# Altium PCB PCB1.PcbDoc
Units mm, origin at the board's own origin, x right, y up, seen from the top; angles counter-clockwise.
Board outline 48.01 x 48.26 mm, 2 copper layers (Top Layer, Bottom Layer); 27 components, 29 nets, 112 pads, 21 vias.
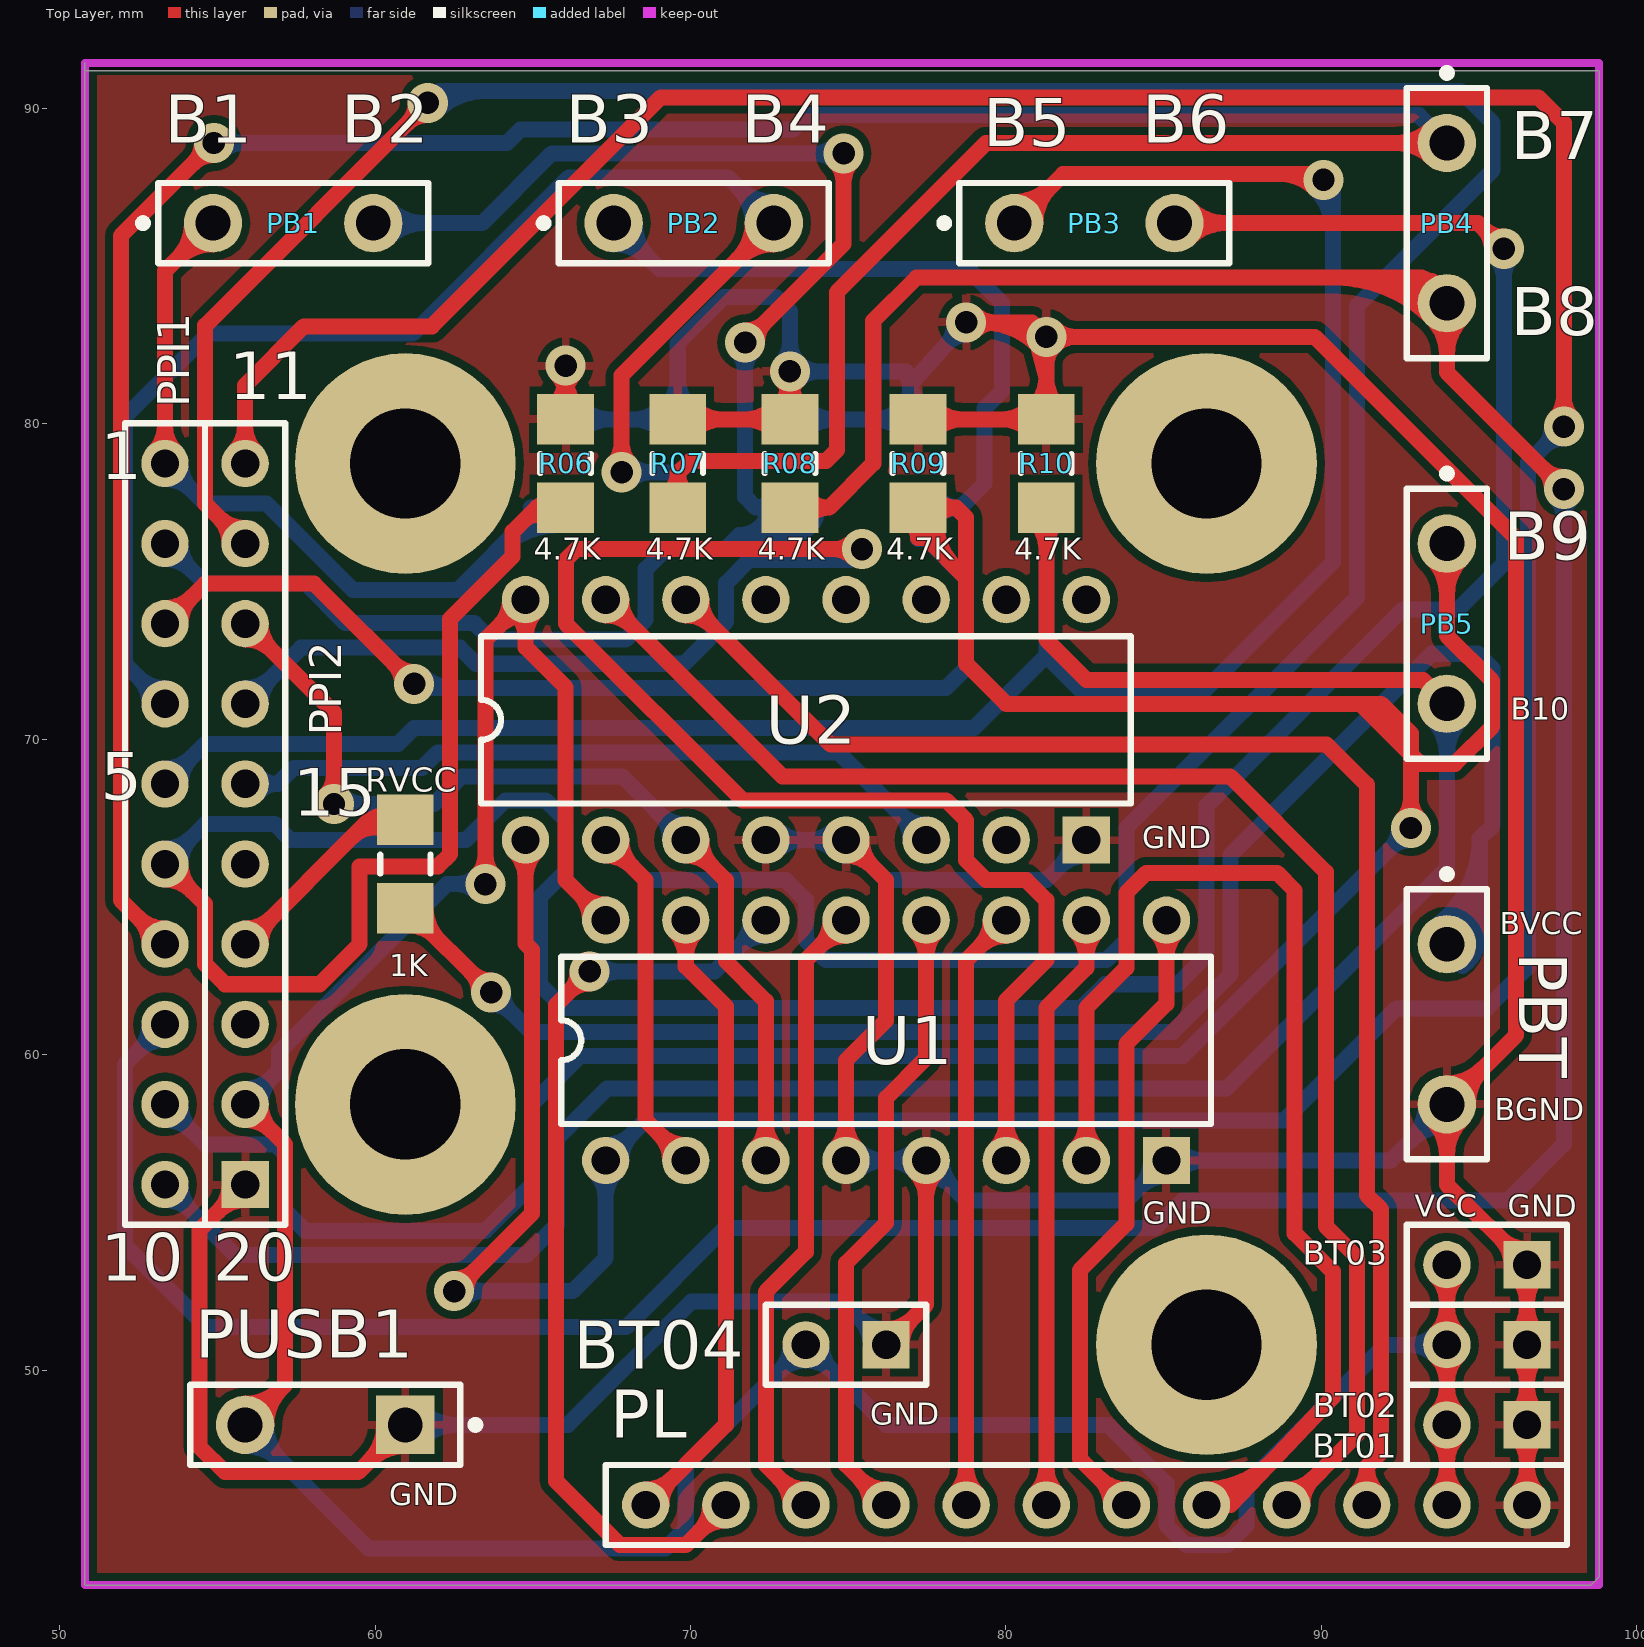
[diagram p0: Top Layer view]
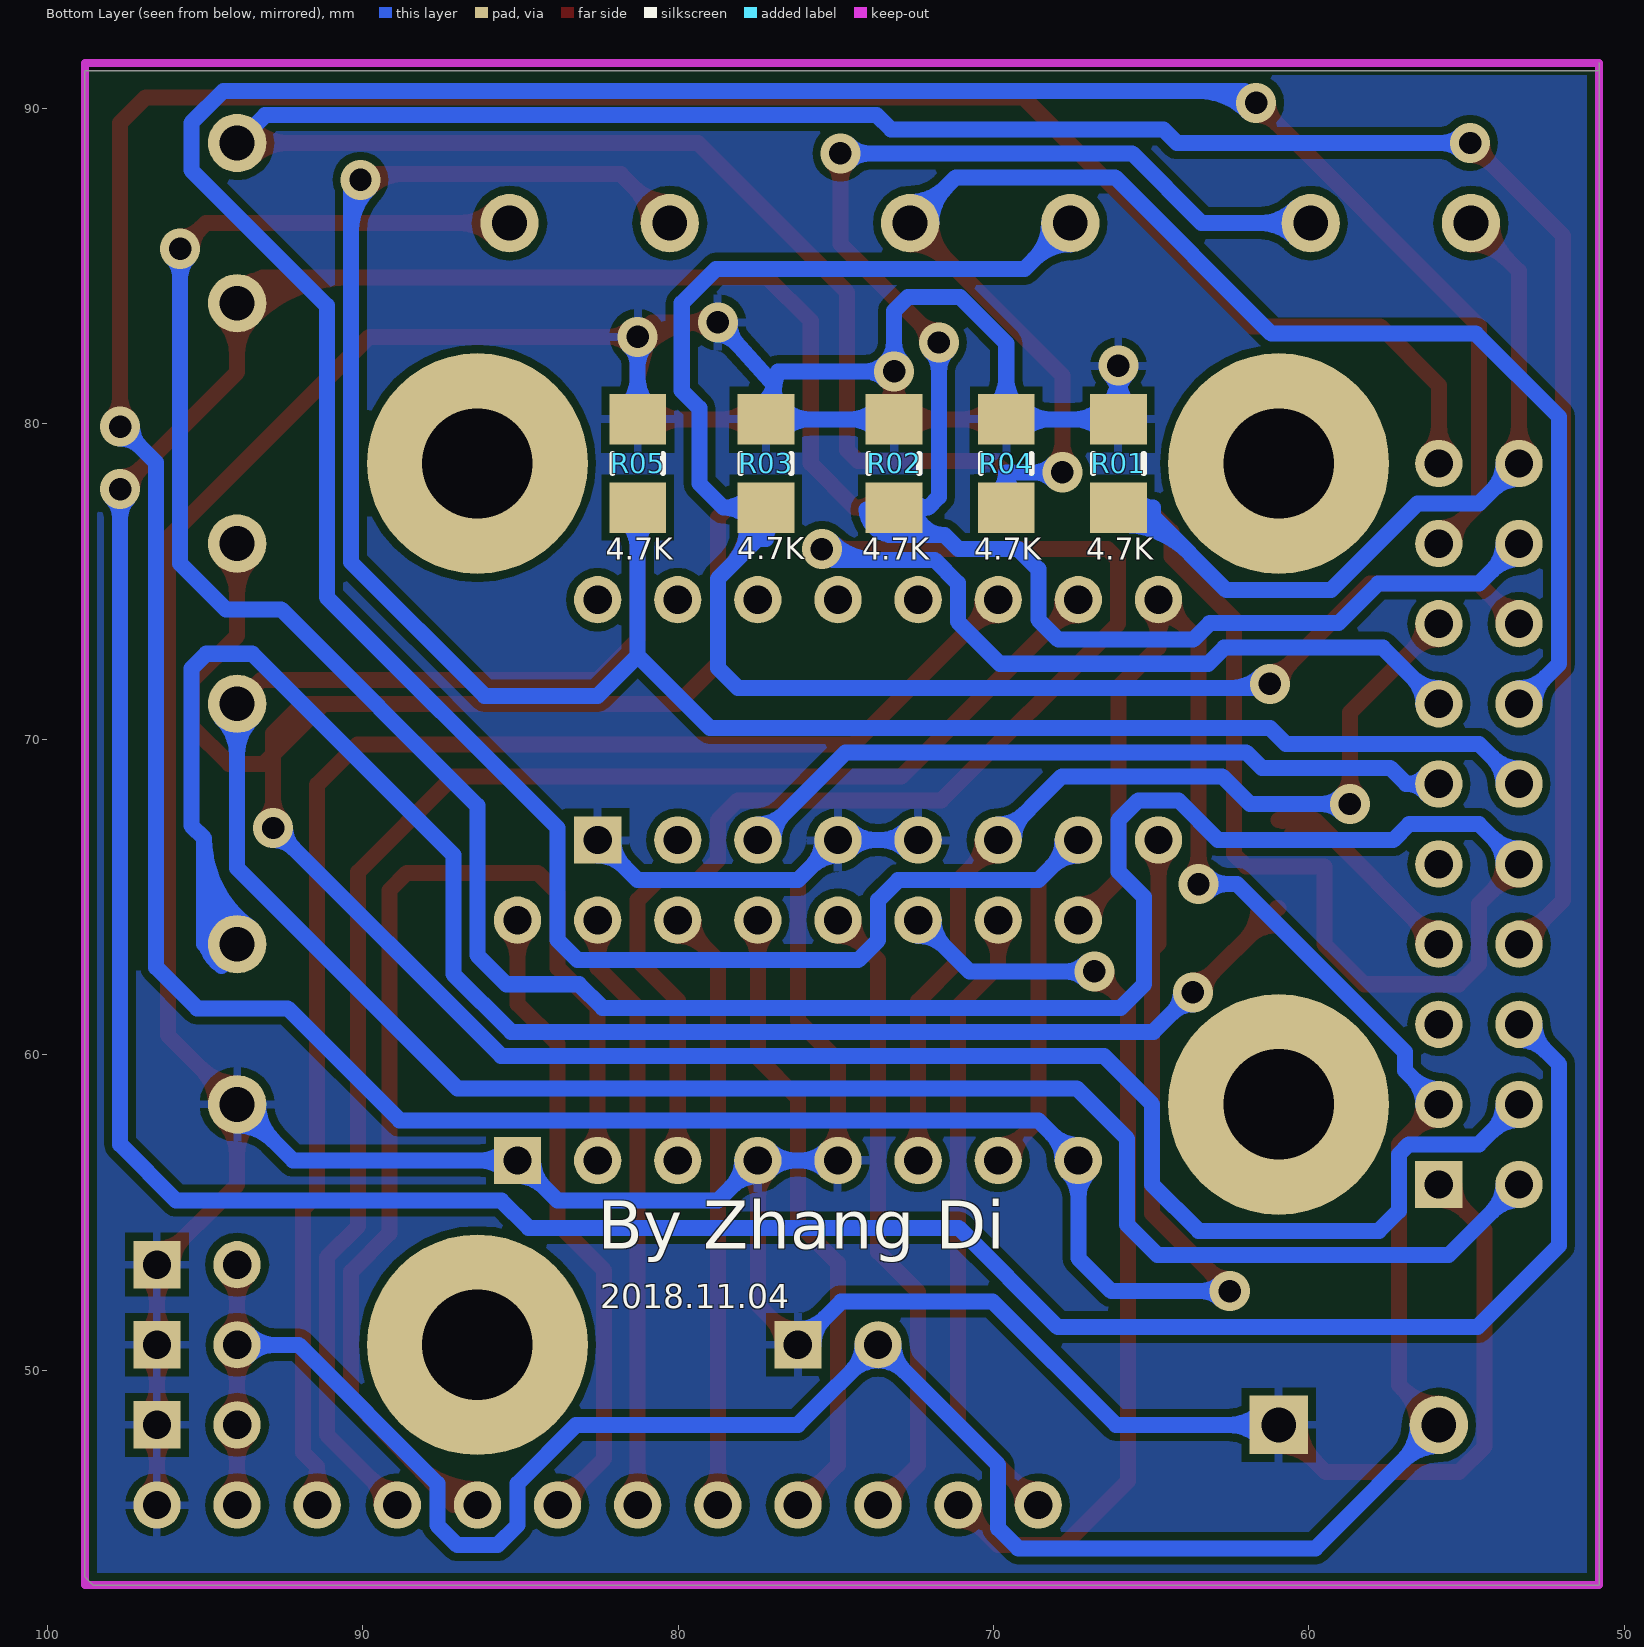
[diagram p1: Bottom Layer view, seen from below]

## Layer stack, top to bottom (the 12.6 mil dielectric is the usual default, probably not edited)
Top Layer: signal copper 0.0356
Dielectric: dielectric 0.32, FR-4, Dk 4.8
Bottom Layer: signal copper 0.0356

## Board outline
51.054,91.186 98.806,91.186 98.806,43.434 98.552,43.18 50.8,43.18 50.8,91.44 50.8,91.186

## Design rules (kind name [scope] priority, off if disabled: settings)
Clearance [All] p1: gap=0.254
ComponentClearance [All] p1: gap=0.254 collisioncheckmode=3 verticalgap=0.254
PolygonConnect [All] p1: connectstyle=Relief reliefconductorwidth=0.254 reliefentries=4 polygonreliefangle="90 Angle"
RoutingVias [All] p1: holewidth=0.711 width=1.27 viastyle="Through Hole" minholewidth=0.711 minwidth=1.27 maxholewidth=0.711 maxwidth=1.27
SolderMaskExpansion [All] p1: expansion=0.102
TestPointUsage [All] p1: valid=0 allowmultiple=FALSE
Testpoint [All] p1: side=15 testpointundercomponent=TRUE minsize=1.016 maxsize=2.54 preferedsize=1.524 minholesize=0 maxholesize=1.016 preferedholesize=0.813 testpointgrid=0.025 style=1023 order=0-112345678
Width Width_2 [All] p1: maxlimit=0.762 minlimit=0.381 preferedwidth=0.508
Width Width_1 [InNet('VCC')] p2: maxlimit=0.762 minlimit=0.508 preferedwidth=0.762
Width [InNet('GND')] p3: maxlimit=0.762 minlimit=0.508 preferedwidth=0.762
18 further rules are at their usual default settings.

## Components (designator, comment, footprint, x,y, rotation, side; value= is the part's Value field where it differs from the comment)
BT01 "Header 2" HDR1X2 96.52,48.26 r180 top
BT02 "Header 2" HDR1X2 96.52,50.8 r180 top
BT03 "Header 2" HDR1X2 96.52,53.34 r180 top
BT04 "Header 2" HDR1X2 76.2,50.8 r180 top
PB1 "Header 2" SPST-2#1 57.404,86.36 r0 top
PB2 "Header 2" SPST-2#1 70.104,86.36 r0 top
PB3 "Header 2" SPST-2#1 82.804,86.36 r0 top
PB4 "Header 2" SPST-2#1 93.98,86.36 r270 top
PB5 "Header 2" SPST-2#1 93.98,73.66 r270 top
PBT "Header 2" SPST-2#1 93.98,60.96 r270 top
PL "Header 12" HDR1X12 68.58,45.72 r0 top
PPI1 "Header 10" HDR1X10#1 53.34,78.74 r270 top
PPI2 "Header 10" HDR1X10#2 55.88,78.74 r270 top
PUSB1 "Header 2" SPST-2#2 58.42,48.26 r180 top
R01 "Res1" 3216[1206] 66.04,78.74 r270 bottom
R02 "Res1" 3216[1206] 73.152,78.74 r270 bottom
R03 "Res1" 3216[1206] 77.216,78.74 r270 bottom
R04 "Res1" 3216[1206] 69.596,78.74 r270 bottom
R05 "Res1" 3216[1206] 81.28,78.74 r270 bottom
R06 "Res1" 3216[1206] 66.04,78.74 r270 top
R07 "Res1" 3216[1206] 69.596,78.74 r270 top
R08 "Res1" 3216[1206] 73.152,78.74 r270 top
R09 "Res1" 3216[1206] 77.216,78.74 r270 top
R10 "Res1" 3216[1206] 81.28,78.74 r270 top
RVCC "Res1" 3216[1206] 60.96,66.04 r90 top
U1 "SN74HC138D" DIP-16 76.2,60.452 r0 top
U2 "SN74HC138D" DIP-16 73.66,70.612 r0 top

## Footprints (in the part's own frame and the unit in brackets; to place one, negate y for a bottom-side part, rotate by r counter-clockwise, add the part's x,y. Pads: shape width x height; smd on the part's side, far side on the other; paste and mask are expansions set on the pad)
3216[1206] [mm] "Chip Resistor; Body 3.2 x 1.6 mm (LxW typ)"
  rect 1.6x1.8 smd: 1(-1.4,0) 2(1.4,0)
  silkscreen extent -0.3,-0.8 0.3,0.8
DIP-16 [mm] "DIP; 16 Leads; Row Spacing 7.62 mm; Pitch 2.54 mm"
  round 1.5 hole 0.9: 1(-8.89,-3.81) 2(-6.35,-3.81) 3(-3.81,-3.81) 4(-1.27,-3.81) 5(1.27,-3.81) 6(3.81,-3.81) 7(6.35,-3.81) 9(8.89,3.81) 10(6.35,3.81) 11(3.81,3.81) 12(1.27,3.81) 13(-1.27,3.81) 14(-3.81,3.81) 15(-6.35,3.81) 16(-8.89,3.81)
  rect 1.5x1.5 hole 0.9: 8(8.89,-3.81)
  silkscreen extent -10.3,-2.65 10.3,2.65
HDR1X2 [mm] "Connector; Header; 2 Position"
  rect 1.5x1.5 hole 0.9: 1(0,0)
  round 1.5 hole 0.9: 2(2.54,0)
  silkscreen extent -1.27,-1.27 3.81,1.27
HDR1X10#1 [mm] "Connector; Header; 10 Position"
  round 1.5 hole 0.9: 1(0,0) 2(2.54,0) 3(5.08,0) 4(7.62,0) 5(10.16,0) 6(12.7,0) 7(15.24,0) 8(17.78,0) 9(20.32,0) 10(22.86,0)
  silkscreen extent -1.27,-1.27 24.13,1.27
HDR1X10#2 [mm] "Connector; Header; 10 Position"
  round 1.5 hole 0.9: 1(0,0) 2(2.54,0) 3(5.08,0) 4(7.62,0) 5(10.16,0) 6(12.7,0) 7(15.24,0) 8(17.78,0) 9(20.32,0)
  rect 1.5x1.5 hole 0.9: 10(22.86,0)
  silkscreen extent -1.27,-1.27 24.13,1.27
HDR1X12 [mm] "Connector; Header; 12 Position"
  round 1.5 hole 0.9: 1(0,0) 2(2.54,0) 3(5.08,0) 4(7.62,0) 5(10.16,0) 6(12.7,0) 7(15.24,0) 8(17.78,0) 9(20.32,0) 10(22.86,0) 11(25.4,0) 12(27.94,0)
  silkscreen extent -1.27,-1.27 29.21,1.27
SPST-2#1 [mm] "Circuit Breaker; 2 Leads"
  round 1.85 hole 1.1: 1(-2.54,0) 2(2.54,0)
  silkscreen extent -4.89,-1.27 4.28,1.27
SPST-2#2 [mm] "Circuit Breaker; 2 Leads"
  rect 1.85x1.85 hole 1.1: 1(-2.54,0)
  round 1.85 hole 1.1: 2(2.54,0)
  silkscreen extent -4.89,-1.27 4.28,1.27

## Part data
BT01 BT02 BT03 BT04 PB1 PB2 PB3 PB4 PB5 PBT PUSB1: "Header, 2-Pin"
PL: "Header, 12-Pin"
PPI1 PPI2: "Header, 10-Pin"
R01 R02 R03 R04 R05 R06 R07 R08 R09 R10 RVCC: "Resistor"
U1 U2: "3-Line to 8-Line Decoder / Demultiplexer"

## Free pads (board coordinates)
  round 7 hole 3.5: 0(86.36,78.74) 1(60.96,78.74) 3(86.36,50.8)
  round 7 hole 3.5 paste+0: 2(60.96,58.42)

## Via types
v1: diameter 1.27, hole 0.711, Top Layer to Bottom Layer, 21 vias

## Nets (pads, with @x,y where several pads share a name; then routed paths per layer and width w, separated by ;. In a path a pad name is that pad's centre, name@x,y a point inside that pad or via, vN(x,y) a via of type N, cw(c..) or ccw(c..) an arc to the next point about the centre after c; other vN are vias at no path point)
GND: BT01.1 BT02.1 BT03.1 BT04.1 PBT.2 PL.12 PPI2.10 PUSB1.1 R01.1 R02.1 R03.1 R04.1 R05.1 R06.1 R07.1 R08.1 R09.1 R10.1 U1.4 U1.5 U1.8 U2.4 U2.5 U2.8 | length 285
  Top Layer w0.508: PPI2.10@55.384,55.88 cw(c54.187,55.88) 55.033,55.033 cw(c55.88,54.187) PPI2.10@55.88,55.384 ; PPI2.10 54.432,54.432 54.432,47.574 55.245,46.761 59.461,46.761 PUSB1.1 ; PUSB1.1@60.289,48.26 cw(c58.669,48.26) 59.815,47.115 cw(c60.96,45.969) PUSB1.1@60.96,47.589 ; R06.1@65.654,80.526 ccw(c64.722,81.458) 66.04,81.458 ccw(c67.358,81.458) R06.1@66.426,80.526 ; v1@65.771,81.569 cw(c65.12,80.919) 66.04,80.919 cw(c66.96,80.919) v1@66.309,81.569 ; R06.1 v1(66.04,81.839) ; R07.1 R08.1 v1(73.152,81.661) ; R07.1@70.082,79.754 cw(c71.014,78.822) 71.014,80.14 cw(c71.014,81.458) R07.1@70.082,80.526 ; R08.1@72.666,79.754 ccw(c71.734,78.822) 71.734,80.14 ccw(c71.734,81.458) R08.1@72.666,80.526 ; R08.1@72.766,80.526 ccw(c71.834,81.458) 73.152,81.458 ccw(c74.47,81.458) R08.1@73.538,80.526 ; v1@72.883,81.392 cw(c72.232,80.741) 73.152,80.741 cw(c74.072,80.741) v1@73.421,81.392 ; U1.4@74.579,56.993 ccw(c73.733,57.839) 74.93,57.839 ccw(c76.127,57.839) U1.4@75.281,56.993 ; U1.4 74.93,59.817 76.2,61.087 76.2,65.532 U2.5 ; U2.5@74.93,66.306 cw(c74.93,65.109) 75.777,65.955 cw(c76.623,66.802) U2.5@75.426,66.802 ; BT04.1 77.47,52.07 U1.5 ; BT04.1@76.2,51.296 ccw(c76.2,52.493) 77.047,51.647 ccw(c77.893,50.8) BT04.1@76.696,50.8 ; U1.5@77.119,56.291 cw(c76.273,55.445) 77.47,55.445 cw(c78.667,55.445) U1.5@77.821,56.291 ; R09.1 R10.1 81.28,81.483 ; R09.1@77.702,79.754 cw(c78.634,78.822) 78.634,80.14 cw(c78.634,81.458) R09.1@77.702,80.526 ; v1(78.74,83.21) 80.823,83.21 ; v1@79.009,82.941 cw(c79.66,82.291) 79.66,83.21 cw(c79.66,84.13) v1@79.009,83.48 ; v1@79.256,83.21 cw(c79.256,80.73) 81.011,82.484 cw(c80.36,81.833) 81.28,81.833 cw(c82.2,81.833) 81.549,82.484 cw(c82.2,81.833) 82.2,82.753 cw(c82.2,83.673) v1@81.549,83.023 ; 80.483,83.21 cw(c80.483,81.956) v1@81.37,82.843 ; R10.1@80.794,79.754 ccw(c79.862,78.822) 79.862,80.14 ccw(c79.862,81.458) R10.1@80.794,80.526 ; R10.1@80.894,80.526 ccw(c79.962,81.458) 81.28,81.458 ccw(c82.598,81.458) R10.1@81.666,80.526 ; PBT.2@93.506,57.946 cw(c92.36,56.8) 93.98,56.8 cw(c95.6,56.8) PBT.2@94.454,57.946 ; PBT.2@93.98,59.091 ccw(c93.98,60.711) 95.125,59.565 ccw(c96.271,58.42) PBT.2@94.651,58.42 ; BT03.1@96.024,53.34 ccw(c94.827,53.34) 95.673,54.187 ccw(c96.52,55.033) BT03.1@96.52,53.836 ; PL.12@96.169,46.071 ccw(c95.323,46.917) 96.52,46.917 ccw(c97.717,46.917) PL.12@96.871,46.071 ; BT01.1@96.169,47.909 cw(c95.323,47.063) 96.52,47.063 cw(c97.717,47.063) BT01.1@96.871,47.909 ; BT01.1@96.169,48.611 ccw(c95.323,49.457) 96.52,49.457 ccw(c97.717,49.457) BT01.1@96.871,48.611 ; BT02.1@96.169,50.449 cw(c95.323,49.603) 96.52,49.603 cw(c97.717,49.603) BT02.1@96.871,50.449 ; BT02.1@96.169,51.151 ccw(c95.323,51.997) 96.52,51.997 ccw(c97.717,51.997) BT02.1@96.871,51.151 ; BT03.1@96.169,52.989 cw(c95.323,52.143) 96.52,52.143 cw(c97.717,52.143) BT03.1@96.871,52.989 ; PL.12 BT01.1 BT02.1 BT03.1 93.98,55.88 PBT.2 96.175,60.615 96.175,76.367 89.789,82.753 v1(81.28,82.753) ; 80.823,83.21 v1@80.944,82.753 ; 80.823,83.21 80.823,82.753 v1@80.944,82.753 ; v1@80.944,82.753 v1(81.28,82.753) ; v1@80.944,82.753 80.966,82.67 81.28,81.483 ; 81.28,81.483 v1(81.28,82.753)
  Bottom Layer w0.508: PUSB1.1 66.116,48.26 70.028,52.172 74.828,52.172 BT04.1 ; PUSB1.1@61.434,47.786 cw(c62.58,46.64) 62.58,48.26 cw(c62.58,49.88) PUSB1.1@61.434,48.734 ; R01.1@65.654,80.526 ccw(c64.722,81.458) 66.04,81.458 ccw(c67.358,81.458) R01.1@66.426,80.526 ; v1@65.771,81.569 cw(c65.12,80.919) 66.04,80.919 cw(c66.96,80.919) v1@66.309,81.569 ; v1(66.04,81.839) R01.1 R04.1 69.596,82.55 71.069,84.023 72.707,84.023 73.152,83.579 v1(73.152,81.661) 76.835,81.661 76.947,81.213 ; R01.1@66.526,79.754 cw(c67.458,78.822) 67.458,80.14 cw(c67.458,81.458) R01.1@66.526,80.526 ; R04.1@69.11,79.754 ccw(c68.178,78.822) 68.178,80.14 ccw(c68.178,81.458) R04.1@69.11,80.526 ; R04.1@69.21,80.526 ccw(c68.278,81.458) 69.596,81.458 ccw(c70.914,81.458) R04.1@69.982,80.526 ; U2.4 U2.5 76.2,65.532 81.28,65.532 U2.8 ; U2.4@72.741,66.451 cw(c73.587,65.605) 73.587,66.802 cw(c73.587,67.999) U2.4@72.741,67.153 ; v1@72.883,81.93 ccw(c72.232,82.581) 73.152,82.581 ccw(c74.072,82.581) 73.421,81.93 ccw(c74.072,82.581) 74.072,81.661 ccw(c74.072,80.741) v1@73.421,81.392 ; R02.1 R03.1 ; R02.1@73.638,79.754 cw(c74.57,78.822) 74.57,80.14 cw(c74.57,81.458) R02.1@73.638,80.526 ; U2.5@74.579,66.451 ccw(c73.733,65.605) 73.733,66.802 ccw(c73.733,67.999) U2.5@74.579,67.153 ; U1.4 U1.5 78.74,55.372 83.82,55.372 U1.8 92.202,56.642 PBT.2 ; U2.5@74.93,66.306 cw(c74.93,65.109) 75.777,65.955 cw(c76.623,66.802) U2.5@75.426,66.802 ; U1.4@75.281,56.291 cw(c76.127,55.445) 76.127,56.642 cw(c76.127,57.839) U1.4@75.281,56.993 ; BT04.1@75.704,50.8 ccw(c74.507,50.8) 75.353,51.647 ccw(c76.2,52.493) BT04.1@76.2,51.296 ; R03.1@76.73,79.754 ccw(c75.798,78.822) 75.798,80.14 ccw(c75.798,81.458) R03.1@76.73,80.526 ; U1.5@77.119,56.291 ccw(c76.273,55.445) 76.273,56.642 ccw(c76.273,57.839) U1.5@77.119,56.993 ; U1.5@77.47,56.146 cw(c77.47,54.949) 78.317,55.795 cw(c79.163,56.642) U1.5@77.966,56.642 ; v1@78.36,83.19 cw(c77.441,83.14) 78.126,82.526 cw(c78.81,81.911) v1@78.761,82.83 ; v1(78.74,83.21) 76.947,81.213 ; R05.1@80.894,80.526 ccw(c79.962,81.458) 81.28,81.458 ccw(c82.598,81.458) R05.1@81.666,80.526 ; v1@81.011,82.484 cw(c80.36,81.833) 81.28,81.833 cw(c82.2,81.833) v1@81.549,82.484 ; R05.1 v1(81.28,82.753) ; U2.8@82.054,66.802 cw(c80.857,66.802) 81.703,65.955 cw(c82.55,65.109) U2.8@82.55,66.306 ; U1.8@84.594,56.642 cw(c83.397,56.642) 84.243,55.795 cw(c85.09,54.949) U1.8@85.09,56.146 ; U1.8@85.441,56.291 cw(c86.287,55.445) 86.287,56.642 cw(c86.287,57.839) U1.8@85.441,56.993 ; PBT.2@93.309,58.42 cw(c91.689,58.42) 92.835,57.275 cw(c93.98,56.129) PBT.2@93.98,57.749 ; 76.947,81.213 R03.1 ; 76.947,81.213 R03.1 ; R03.1@76.739,80.535 ccw(c76.237,81.06) 76.941,81.236 cw(c76.237,81.06) R03.1@76.739,80.535 ; 76.947,81.215 ccw(c77.904,81.455) 77.397,80.608 cw(c77.904,81.455) 76.947,81.215
NetPB1_1: PB1.1 PPI1.1 R01.2 | length 37.3
  Top Layer w0.508: PPI1.1@52.989,79.091 ccw(c52.143,79.937) 53.34,79.937 ccw(c54.537,79.937) PPI1.1@53.691,79.091 ; PPI1.1 53.34,84.836 PB1.1 ; PB1.1@54.193,86.36 cw(c52.573,86.36) 53.719,85.215 cw(c54.864,84.069) PB1.1@54.864,85.689
  Bottom Layer w0.508: PPI1.1@53.34,78.244 cw(c53.34,77.047) 54.187,77.893 cw(c55.033,78.74) PPI1.1@53.836,78.74 ; PPI1.1 54.61,77.47 56.562,77.47 59.305,74.727 62.615,74.727 64.948,77.06 64.948,77.34 ; 63.793,75.905 cw(c65.94,73.757) R01.2@65.94,76.794 ; 64.592,76.704 cw(c65.24,76.055) R01.2@65.679,76.861 ; 64.66,76.772 cw(c65.94,75.492) R01.2@65.94,77.302 ; 65.072,77.184 cw(c65.579,76.677) R01.2@65.922,77.307 ; R01.2@65.479,77.048 ccw(c64.948,76.712) 64.948,77.34 ; R01.2@65.479,77.632 cw(c64.948,77.968) 64.948,77.34 ; R01.2 64.948,77.34
NetPB1_2: PB1.2 PPI1.2 R02.2 | length 70.8
  Top Layer w0.508: v1(71.73,82.575) 74.854,85.7 v1(74.854,88.57) ; v1@71.73,82.956 ccw(c71.73,83.876) 72.38,83.226 ccw(c73.03,82.575) v1@72.111,82.575 ; v1@74.584,88.3 cw(c73.934,87.65) 74.854,87.65 cw(c75.774,87.65) v1@75.123,88.3
  Bottom Layer w0.508: PPI1.2@53.34,75.704 cw(c53.34,74.507) 54.187,75.353 cw(c55.033,76.2) PPI1.2@53.836,76.2 ; PPI1.2 54.61,74.93 57.81,74.93 59.062,73.678 63.144,73.678 63.67,73.152 67.945,73.152 68.58,73.787 68.58,75.387 69.215,76.022 71.107,76.022 71.551,76.467 ; PB1.2 63.398,86.36 65.608,88.57 v1(74.854,88.57) ; PB1.2@60.418,85.886 cw(c61.564,84.74) 61.564,86.36 cw(c61.564,87.98) PB1.2@60.418,86.834 ; v1@71.46,82.306 cw(c70.81,81.656) 71.73,81.656 cw(c72.649,81.656) v1@71.999,82.306 ; v1(71.73,82.575) 71.73,77.683 72.072,77.34 ; 72.089,76.467 ccw(c72.089,77.394) R02.2@73.014,77.342 ; R02.2@72.507,77.37 cw(c71.551,77.424) 71.551,76.467 ; R02.2@72.588,77.053 ccw(c72.073,76.734) 72.073,77.34 ; R02.2@72.588,77.627 cw(c72.073,77.946) 72.073,77.34 ; 72.626,76.467 ccw(c72.626,77.364) R02.2@73.521,77.314 ; 73.163,76.467 ccw(c73.163,77.334) R02.2@74.028,77.286 ; v1@74.584,88.3 ccw(c73.934,87.65) 73.934,88.57 ccw(c73.934,89.49) v1@74.584,88.839 ; 71.551,76.467 73.152,76.467 R02.2 72.072,77.34
NetPB2_1: PB2.1 PPI1.3 R03.2 | length 69.7
  Top Layer w0.508: PPI1.3 54.61,74.93 58.064,74.93 v1(61.239,71.755) ; PPI1.3@53.34,74.156 ccw(c53.34,75.353) 54.187,74.507 ccw(c55.033,73.66) PPI1.3@53.836,73.66 ; v1@60.858,71.755 ccw(c59.939,71.755) 60.589,72.405 ccw(c61.239,73.056) v1@61.239,72.136
  Bottom Layer w0.508: v1(61.239,71.755) 61.366,71.628 78.105,71.628 78.74,72.263 78.74,75.082 77.47,76.352 77.216,76.352 ; v1@61.509,72.024 ccw(c62.466,72.981) 62.466,71.628 ; PB2.1@67.564,85.689 cw(c67.564,84.069) 68.709,85.215 cw(c69.855,86.36) PB2.1@68.235,86.36 ; PB2.1 69.012,84.912 78.791,84.912 79.883,83.82 79.883,81.051 79.324,80.493 79.324,78.105 78.559,77.34 ; R03.2@76.926,76.878 cw(c76.596,76.352) 77.216,76.352 ; R03.2@76.953,76.932 cw(c76.434,76.347) 77.216,76.347 cw(c77.756,76.347) R03.2@77.537,76.841 ; R03.2@77.353,77.331 ccw(c78.579,77.029) 77.686,76.136 ; R03.2@77.506,76.878 ccw(c77.836,76.352) 77.216,76.352 ; R03.2@77.718,76.971 cw(c78.559,76.198) 78.559,77.34 ; R03.2@77.718,77.709 ccw(c78.559,78.482) 78.559,77.34 ; R03.2@77.846,77.209 ccw(c79.601,76.777) 78.323,75.499 ; 77.216,76.352 R03.2 78.559,77.34
NetPB2_2: PB2.2 PPI1.4 R04.2 | length 58.2
  Top Layer w0.508: v1@67.549,78.73 ccw(c66.898,79.38) 67.818,79.38 ccw(c68.738,79.38) v1@68.087,78.73 ; v1(67.818,78.461) 67.818,81.534 PB2.2 ; PB2.2@71.973,86.36 cw(c70.353,86.36) 71.499,85.215 cw(c72.644,84.069) PB2.2@72.644,85.689
  Bottom Layer w0.508: PPI1.4@52.844,71.12 ccw(c51.647,71.12) 52.493,71.967 ccw(c53.34,72.813) PPI1.4@53.34,71.616 ; PPI1.4 52.07,72.39 52.07,80.213 54.712,82.855 61.189,82.855 66.142,87.808 71.196,87.808 PB2.2 ; v1(67.818,78.461) 69.596,78.461 ; v1@68.087,78.191 cw(c68.738,77.541) 68.738,78.461 cw(c68.738,79.38) v1@68.087,78.73 ; R04.2@69.26,77.77 ccw(c68.719,78.461) 69.596,78.461 ; R04.2 69.596,78.461 ; R04.2@69.932,77.77 cw(c70.473,78.461) 69.596,78.461 ; PB2.2@71.973,86.36 ccw(c70.353,86.36) 71.499,87.505 ccw(c72.644,88.651) PB2.2@72.644,87.031
NetPB3_1: PB3.1 PPI1.5 R05.2 | length 77.7
  Top Layer w0.508: PB3.1 81.813,87.909 89.891,87.909 v1(90.068,87.732) ; PB3.1@80.264,87.031 ccw(c80.264,88.651) 81.409,87.505 ccw(c82.555,86.36) PB3.1@80.935,86.36 ; 88.719,87.909 cw(c88.719,86.383) v1@89.799,87.462
  Bottom Layer w0.508: PPI1.5 54.61,69.85 60.73,69.85 61.238,70.358 78.994,70.358 81.28,72.644 ; PPI1.5@53.34,69.076 ccw(c53.34,70.273) 54.187,69.427 ccw(c55.033,68.58) PPI1.5@53.836,68.58 ; R05.2@80.894,76.954 cw(c79.962,76.022) 81.28,76.022 cw(c82.598,76.022) R05.2@81.666,76.954 ; R05.2 81.28,72.644 ; v1@89.799,87.462 cw(c88.413,86.076) 90.373,86.076 ; v1(90.068,87.732) 90.373,87.427 90.373,75.616 86.131,71.374 82.55,71.374 81.28,72.644
NetPB3_2: PB3.2 PPI1.6 R06.2 | length 121.1
  Top Layer w0.508: PPI1.6@53.34,65.544 cw(c53.34,64.347) 54.187,65.193 cw(c55.033,66.04) PPI1.6@53.836,66.04 ; PPI1.6 54.61,64.77 54.61,62.865 55.245,62.23 58.242,62.23 59.512,63.5 59.512,65.964 61.989,65.964 62.382,66.358 62.382,73.814 64.364,75.795 64.364,76.578 65.126,77.34 ; 64.67,76.885 cw(c65.717,75.838) R06.2@65.934,77.302 ; 64.718,76.933 cw(c65.147,76.504) R06.2@65.564,76.944 ; 65.087,77.302 cw(c65.506,76.883) R06.2@65.914,77.312 ; R06.2@65.435,77.133 ccw(c65.126,77.006) 65.126,77.34 ; R06.2@65.435,77.547 cw(c65.126,77.674) 65.126,77.34 ; R06.2 65.126,77.34 ; PB3.2 94.971,86.36 v1(95.783,85.547) ; PB3.2@85.818,85.886 cw(c86.964,84.74) 86.964,86.36 cw(c86.964,87.98) PB3.2@85.818,86.834 ; v1@95.402,85.547 ccw(c94.483,85.547) 95.133,86.198 ccw(c95.783,86.848) v1@95.783,85.928
  Bottom Layer w0.508: PPI1.6 54.61,67.31 56.82,67.31 57.328,66.802 62.877,66.802 64.135,68.06 65.405,68.06 66.04,67.425 66.04,65.811 65.222,64.993 65.222,62.23 65.972,61.48 82.391,61.48 83.141,62.23 85.44,62.23 86.36,63.15 86.36,67.89 92.586,74.116 94.335,74.116 95.783,75.565 v1(95.783,85.547) ; PPI1.6@53.34,66.536 ccw(c53.34,67.733) 54.187,66.887 ccw(c55.033,66.04) PPI1.6@53.836,66.04 ; v1@95.514,85.278 cw(c94.864,84.627) 95.783,84.627 cw(c96.703,84.627) v1@96.053,85.278
NetPB4_1: PB4.1 PPI1.7 R07.2 | length 108.6
  Top Layer w0.508: PPI1.7@52.844,63.5 ccw(c51.647,63.5) 52.493,64.347 ccw(c53.34,65.193) PPI1.7@53.34,63.996 ; PPI1.7 51.943,64.897 51.943,85.954 v1(54.889,88.9) ; v1@54.508,88.9 cw(c53.589,88.9) 54.239,88.25 cw(c54.889,87.599) v1@54.889,88.519 ; R07.2@69.271,77.779 ccw(c68.796,78.422) 69.596,78.422 ; R07.2 69.596,78.422 ; R07.2@69.921,77.779 cw(c70.396,78.422) 69.596,78.422 ; PB4.1@93.506,88.426 ccw(c92.36,87.28) 92.36,88.9 ccw(c92.36,90.52) PB4.1@93.506,89.374 ; PB4.1 79.375,88.9 74.64,84.165 74.64,79.161 74.295,78.816 69.99,78.816 69.596,78.422
  Bottom Layer w0.508: v1(54.889,88.9) 64.186,88.9 64.618,89.332 73.249,89.332 73.703,89.786 93.094,89.786 PB4.1 ; v1@55.159,88.631 cw(c55.809,87.98) 55.809,88.9 cw(c55.809,89.82) v1@55.159,89.169
NetPB4_2: PB4.2 PPI1.8 R08.2 | length 128.1
  Top Layer w0.508: R08.2 74.394,77.34 ; R08.2@73.677,76.997 cw(c74.394,76.42) 74.394,77.34 ; R08.2@73.677,77.683 ccw(c74.394,78.26) 74.394,77.34 ; 90.398,84.633 cw(c90.398,80.238) 93.506,83.346 cw(c92.36,82.2) 93.98,82.2 cw(c95.6,82.2) PB4.2@94.454,83.346 ; 91.624,84.633 cw(c91.624,81.464) PB4.2@93.865,83.705 ; 92.851,84.633 cw(c92.851,82.691) PB4.2@94.224,84.064 ; v1@97.307,77.927 ccw(c96.388,77.927) 97.038,78.578 ccw(c97.688,79.228) v1@97.688,78.308 ; v1(97.688,77.927) 93.98,81.636 PB4.2 93.167,84.633 77.165,84.633 75.794,83.261 75.794,78.74 74.394,77.34
  Bottom Layer w0.508: PPI1.8@52.844,60.96 cw(c51.647,60.96) 52.493,60.113 cw(c53.34,59.267) PPI1.8@53.34,60.464 ; PPI1.8 52.07,59.69 52.07,53.95 54.661,51.359 67.959,51.359 71.108,54.508 84.734,54.508 85.598,55.372 95.91,55.372 97.688,57.15 v1(97.688,77.927) ; v1@97.419,77.658 cw(c96.769,77.007) 97.688,77.007 cw(c98.608,77.007) v1@97.958,77.658
NetPB5_1: PB5.1 PPI1.9 R09.2 | length 102.5
  Top Layer w0.508: R09.2@76.936,76.871 cw(c76.641,76.378) 77.216,76.378 ; R09.2@76.961,76.925 cw(c76.49,76.373) 77.216,76.373 cw(c77.717,76.373) R09.2@77.525,76.836 ; R09.2@77.353,77.331 ccw(c78.577,77.048) 77.689,76.159 ; R09.2@77.496,76.871 ccw(c77.791,76.378) 77.216,76.378 ; R09.2@77.749,77.008 cw(c78.422,76.492) 78.422,77.34 ; R09.2@77.749,77.672 ccw(c78.422,78.188) 78.422,77.34 ; R09.2@77.848,77.217 ccw(c79.628,76.804) 78.336,75.512 ; v1@92.568,67.452 ccw(c91.917,68.103) 92.837,68.103 ccw(c93.757,68.103) v1@93.106,67.452 ; v1(92.837,67.183) 92.837,69.52 ; PB5.1@93.506,75.726 cw(c92.36,74.58) 93.98,74.58 cw(c95.6,74.58) PB5.1@94.454,75.726 ; PB5.1 93.98,73.279 95.413,71.846 95.413,70.394 94.234,69.215 93.142,69.215 92.837,69.52 ; 77.216,76.378 77.47,76.378 78.74,75.108 ; 77.216,76.378 R09.2 78.422,77.34 ; 78.422,77.34 78.74,77.023 78.74,75.108 ; 78.74,75.108 78.74,72.39 80.01,71.12 91.237,71.12 ; 91.237,71.12 91.897,71.12 92.837,70.18 92.837,69.52 ; 91.237,71.12 92.837,69.52
  Bottom Layer w0.508: PPI1.9@53.34,57.924 cw(c53.34,56.727) 54.187,57.573 cw(c55.033,58.42) PPI1.9@53.836,58.42 ; PPI1.9 54.61,57.15 56.832,57.15 57.15,56.832 57.15,55.047 57.785,54.412 63.5,54.412 64.968,55.88 64.968,58.42 66.504,59.956 85.61,59.956 v1(92.837,67.183) ; v1@92.456,67.183 cw(c91.536,67.183) 92.187,66.533 cw(c92.837,65.882) v1@92.837,66.802
NetPB5_2: PB5.2 PPI1.10 R10.2 | length 77.7
  Top Layer w0.508: R10.2@80.894,76.954 cw(c79.962,76.022) 81.28,76.022 cw(c82.598,76.022) R10.2@81.666,76.954 ; R10.2 81.28,73.152 82.55,71.882 93.218,71.882 PB5.2
  Bottom Layer w0.508: PPI1.10@53.34,55.384 cw(c53.34,54.187) 54.187,55.033 cw(c55.033,55.88) PPI1.10@53.836,55.88 ; PPI1.10 55.575,53.645 64.795,53.645 65.761,54.61 65.761,57.328 67.361,58.928 86.995,58.928 93.98,65.913 PB5.2 ; PB5.2@93.506,70.646 cw(c92.36,69.5) 93.98,69.5 cw(c95.6,69.5) PB5.2@94.454,70.646
NetPBT_1: PBT.1 RVCC.1 | length 68.5
  Top Layer w0.508: RVCC.1 61.011,64.64 v1(63.678,61.973) ; RVCC.1@61.06,64.094 cw(c61.06,62.895) 61.908,63.743 ; RVCC.1@61.606,64.64 ccw(c63.043,64.64) 62.027,63.624 ; v1@63.297,61.973 ccw(c62.377,61.973) 63.027,62.623 ccw(c63.678,63.274) v1@63.678,62.354
  Bottom Layer w0.508: v1@63.678,61.592 cw(c63.678,60.672) 64.328,61.323 cw(c64.979,61.973) v1@64.059,61.973 ; v1(63.678,61.973) 64.933,60.718 85.292,60.718 87.122,62.547 87.122,66.33 93.499,72.707 94.958,72.707 95.428,72.238 95.428,67.259 95.021,66.853 ; PBT.1@93.587,64.044 ccw(c91.554,66.853) 95.021,66.853 ; PBT.1@93.884,63.632 ccw(c92.274,65.858) 95.021,65.858 ; PBT.1 95.021,63.5 ; PBT.1@94.182,63.22 ccw(c92.993,64.863) 95.021,64.863 ; PBT.1@94.48,62.809 ccw(c93.713,63.869) 95.021,63.869 ; PBT.1@94.591,63.223 cw(c95.021,63.027) 95.021,63.5 ; PBT.1@94.591,63.777 ccw(c95.021,63.973) 95.021,63.5 ; 95.021,63.5 95.021,66.853
NetPL_1: PL.1 U1.15 | length 23.9
  Top Layer w0.508: PL.1 71.12,48.26 71.12,61.53 69.85,62.8 U1.15 ; PL.1@68.58,46.216 ccw(c68.58,47.413) 69.427,46.567 ccw(c70.273,45.72) PL.1@69.076,45.72 ; U1.15@69.499,63.911 cw(c68.653,63.065) 69.85,63.065 cw(c71.047,63.065) U1.15@70.201,63.911
NetPL_2: PL.2 U1.14 | length 36.3
  Top Layer w0.508: v1@66.421,62.636 cw(c65.501,62.636) 66.152,61.986 cw(c66.802,61.336) v1@66.802,62.255 ; v1(66.802,62.636) 65.73,61.564 65.73,46.487 67.767,44.45 69.85,44.45 PL.2 ; PL.2@70.624,45.72 cw(c69.427,45.72) 70.273,44.873 cw(c71.12,44.027) PL.2@71.12,45.224
  Bottom Layer w0.508: v1(66.802,62.636) 70.764,62.636 U1.14 ; v1@67.071,62.367 cw(c67.722,61.717) 67.722,62.636 cw(c67.722,63.556) v1@67.071,62.906 ; U1.14@71.894,64.262 cw(c70.697,64.262) 71.543,63.415 cw(c72.39,62.569) U1.14@72.39,63.766
NetPL_3: PL.3 U1.13 | length 23.9
  Top Layer w0.508: PL.3@73.164,45.72 ccw(c71.967,45.72) 72.813,46.567 ccw(c73.66,47.413) PL.3@73.66,46.216 ; PL.3 72.39,46.99 72.39,52.476 73.66,53.746 73.66,62.992 U1.13 ; U1.13@74.434,64.262 cw(c73.237,64.262) 74.083,63.415 cw(c74.93,62.569) U1.13@74.93,63.766
NetPL_4: PL.4 U1.12 | length 23.9
  Top Layer w0.508: PL.4@75.704,45.72 ccw(c74.507,45.72) 75.353,46.567 ccw(c76.2,47.413) PL.4@76.2,46.216 ; PL.4 74.93,46.99 74.93,53.391 76.2,54.661 76.2,58.623 77.47,59.893 U1.12 ; U1.12@77.119,63.911 cw(c76.273,63.065) 77.47,63.065 cw(c78.667,63.065) U1.12@77.821,63.911
NetPL_5: PL.5 U1.11 | length 22.8
  Top Layer w0.508: PL.5@78.389,46.071 ccw(c77.543,46.917) 78.74,46.917 ccw(c79.937,46.917) PL.5@79.091,46.071 ; PL.5 78.74,62.992 U1.11 ; U1.11@79.514,64.262 cw(c78.317,64.262) 79.163,63.415 cw(c80.01,62.569) U1.11@80.01,63.766
NetPL_6: PL.6 U1.10 | length 22.8
  Top Layer w0.508: PL.6@80.929,46.071 ccw(c80.083,46.917) 81.28,46.917 ccw(c82.477,46.917) PL.6@81.631,46.071 ; PL.6 81.28,61.48 82.55,62.75 U1.10 ; U1.10@82.199,63.911 cw(c81.353,63.065) 82.55,63.065 cw(c83.747,63.065) U1.10@82.901,63.911
NetPL_7: PL.7 U1.9 | length 24.1
  Top Layer w0.508: PL.7@83.324,45.72 ccw(c82.127,45.72) 82.973,46.567 ccw(c83.82,47.413) PL.7@83.82,46.216 ; PL.7 82.347,47.193 82.347,53.162 83.82,54.635 83.82,60.337 85.09,61.607 U1.9 ; U1.9@84.739,63.911 cw(c83.893,63.065) 85.09,63.065 cw(c86.287,63.065) U1.9@85.441,63.911
NetPL_8: PL.8 U1.7 | length 42.6
  Top Layer w0.508: U1.7@82.199,56.993 ccw(c81.353,57.839) 82.55,57.839 ccw(c83.747,57.839) U1.7@82.901,56.993 ; U1.7 82.55,61.48 83.82,62.75 83.82,65.126 84.455,65.761 88.595,65.761 89.154,65.202 89.154,54.331 90.368,53.117 90.368,49.14 87.122,45.72 PL.8 ; PL.8@86.347,46.216 ccw(c86.267,49.299) 88.504,47.176 ; PL.8@86.36,45.708 ccw(c86.312,47.565) 87.659,46.286
NetPL_9: PL.9 U2.15 | length 51.6
  Top Layer w0.508: U2.15@67.31,73.926 cw(c67.31,72.729) 68.157,73.575 cw(c69.003,74.422) U2.15@67.806,74.422 ; U2.15 72.91,68.822 87.109,68.822 90.143,65.788 90.143,54.558 91.13,53.571 91.13,47.95 PL.9 ; PL.9@88.9,46.216 ccw(c88.9,47.413) 89.747,46.567 ccw(c90.593,45.72) PL.9@89.396,45.72
NetPL_10: PL.10 U2.14 | length 51
  Top Layer w0.508: U2.14@69.85,73.926 cw(c69.85,72.729) 70.697,73.575 cw(c71.543,74.422) U2.14@70.346,74.422 ; U2.14 74.447,69.825 90.17,69.825 91.44,68.555 91.44,55.542 91.892,55.09 91.892,47.391 91.44,46.939 PL.10 ; PL.10@91.089,46.071 ccw(c90.243,46.917) 91.44,46.917 ccw(c92.637,46.917) PL.10@91.791,46.071
NetPPI2_1: PPI2.1 U1.1 U2.1 | length 144.5
  Top Layer w0.508: PPI2.1@55.529,79.091 ccw(c54.683,79.937) 55.88,79.937 ccw(c57.077,79.937) PPI2.1@56.231,79.091 ; PPI2.1 55.88,81.218 57.745,83.083 61.798,83.083 69.063,90.348 96.876,90.348 97.688,89.535 v1(97.688,79.908) ; v1(62.509,52.502) 64.968,54.96 64.968,63.322 64.77,63.52 U2.1 ; v1@62.509,52.883 ccw(c62.509,53.803) 63.16,53.152 ccw(c63.81,52.502) v1@62.89,52.502 ; U2.1@64.419,66.451 cw(c63.573,65.605) 64.77,65.605 cw(c65.967,65.605) U2.1@65.121,66.451 ; v1@97.419,80.178 ccw(c96.769,80.828) 97.688,80.828 ccw(c98.608,80.828) v1@97.958,80.178
  Bottom Layer w0.508: v1(62.509,52.502) 66.261,52.502 67.31,53.55 U1.1 68.58,57.912 88.824,57.912 92.38,61.468 95.25,61.468 96.545,62.763 96.545,78.765 v1(97.688,79.908) ; v1@62.779,52.232 cw(c63.429,51.582) 63.429,52.502 cw(c63.429,53.422) v1@62.779,52.771 ; U1.1@66.959,56.291 cw(c66.113,55.445) 67.31,55.445 cw(c68.507,55.445) U1.1@67.661,56.291 ; U1.1@67.31,57.138 ccw(c67.31,58.335) 68.157,57.489 ccw(c69.003,56.642) U1.1@67.806,56.642 ; v1@97.307,79.908 cw(c96.388,79.908) 97.038,79.258 cw(c97.688,78.608) v1@97.688,79.527
NetPPI2_2: PPI2.2 U1.2 U2.2 | length 124.3
  Top Layer w0.508: PPI2.2@55.384,76.2 ccw(c54.187,76.2) 55.033,77.047 ccw(c55.88,77.893) PPI2.2@55.88,76.696 ; PPI2.2 54.61,77.47 54.61,83.109 v1(61.671,90.17) ; v1@61.29,90.17 cw(c60.37,90.17) 61.021,89.52 cw(c61.671,88.869) v1@61.671,89.789 ; U2.2@67.31,66.306 cw(c67.31,65.109) 68.157,65.955 cw(c69.003,66.802) U2.2@67.806,66.802 ; U2.2 68.58,65.532 68.58,57.912 U1.2 ; U1.2@69.354,56.642 ccw(c68.157,56.642) 69.003,57.489 ccw(c69.85,58.335) U1.2@69.85,57.138
  Bottom Layer w0.508: v1@61.581,90.26 cw(c62.276,89.565) 62.276,90.548 ; v1(61.671,90.17) 62.049,90.548 94.415,90.548 95.428,89.535 95.428,88.036 91.135,83.744 91.135,74.498 83.82,67.183 83.82,63.627 83.185,62.992 74.295,62.992 73.66,63.627 73.66,64.897 73.025,65.532 68.58,65.532 U2.2 ; v1@61.941,89.901 cw(c63.503,88.339) 63.503,90.548 ; U2.2@67.31,66.306 cw(c67.31,65.109) 68.157,65.955 cw(c69.003,66.802) U2.2@67.806,66.802
NetPPI2_3: PPI2.3 U1.3 U2.3 | length 40.9
  Top Layer w0.508: PPI2.3@55.88,73.164 cw(c55.88,71.967) 56.727,72.813 cw(c57.573,73.66) PPI2.3@56.376,73.66 ; PPI2.3 58.699,70.841 v1(58.699,67.945) ; v1@58.43,68.214 ccw(c57.78,68.865) 58.699,68.865 ccw(c59.619,68.865) v1@58.969,68.214 ; U2.3@69.85,66.306 cw(c69.85,65.109) 70.697,65.955 cw(c71.543,66.802) U2.3@70.346,66.802 ; U2.3 71.12,65.532 71.12,62.967 72.39,61.697 U1.3 ; U1.3@72.039,56.993 ccw(c71.193,57.839) 72.39,57.839 ccw(c73.587,57.839) U1.3@72.741,56.993
  Bottom Layer w0.508: v1(58.699,67.945) 61.873,67.945 62.75,68.822 67.83,68.822 U2.3 ; v1@58.969,67.676 cw(c59.619,67.025) 59.619,67.945 cw(c59.619,68.865) v1@58.969,68.214 ; U2.3@69.354,66.802 ccw(c68.157,66.802) 69.003,67.649 ccw(c69.85,68.495) U2.3@69.85,67.298
NetPPI2_4: PPI2.4 U1.6 | length 69.5
  Top Layer w0.508: v1@75.169,75.753 ccw(c74.518,75.102) 74.518,76.022 ccw(c74.518,76.942) v1@75.169,76.292 ; v1(75.438,76.022) 66.382,76.022 66.052,75.692 66.052,73.66 71.652,68.06 78.105,68.06 78.74,67.425 78.74,66.167 79.375,65.532 80.645,65.532 81.28,64.897 81.28,62.992 80.01,61.722 U1.6 ; U1.6@79.659,56.993 ccw(c78.813,57.839) 80.01,57.839 ccw(c81.207,57.839) U1.6@80.361,56.993
  Bottom Layer w0.508: PPI2.4 57.658,72.898 62.687,72.898 63.195,72.39 69.799,72.39 71.132,73.723 71.132,74.943 71.869,75.68 75.096,75.68 v1(75.438,76.022) ; PPI2.4@55.88,71.616 ccw(c55.88,72.813) 56.727,71.967 ccw(c57.573,71.12) PPI2.4@56.376,71.12 ; 73.692,75.68 ccw(c73.692,77.768) v1@75.169,76.292
NetPPI2_5: PPI2.5 U2.6 | length 26.5
  Bottom Layer w0.508: PPI2.5 56.921,68.58 ; PPI2.5@56.265,68.267 cw(c56.921,67.735) 56.921,68.58 ; PPI2.5@56.265,68.893 ccw(c56.921,69.425) 56.921,68.58 ; U2.6@76.974,66.802 ccw(c75.777,66.802) 76.623,67.649 ccw(c77.47,68.495) U2.6@77.47,67.298 ; U2.6 74.688,69.584 61.988,69.584 61.492,69.088 57.429,69.088 56.921,68.58
NetPPI2_7: PPI2.7 RVCC.2 | length 12.6
  Top Layer w0.508: PPI2.7 59.82,67.44 ; PPI2.7@55.88,63.996 ccw(c55.88,65.193) 56.727,64.347 ccw(c57.573,63.5) PPI2.7@56.376,63.5 ; 59.3,66.92 cw(c59.964,66.256) RVCC.2@60.53,67.005 ; 59.712,67.332 cw(c60.319,66.726) RVCC.2@60.837,67.41 ; RVCC.2@60.411,67.13 ccw(c59.82,66.723) 59.82,67.44 ; RVCC.2@60.411,67.75 cw(c59.82,68.157) 59.82,67.44 ; RVCC.2 59.82,67.44
VCC: BT01.2 BT02.2 BT03.2 BT04.2 PL.11 PPI2.9 PUSB1.2 U1.16 U2.16 | length 135.1
  Top Layer w0.508: PUSB1.2 57.15,49.53 57.15,57.15 PPI2.9 ; PUSB1.2@55.88,48.931 ccw(c55.88,50.551) 57.025,49.405 ccw(c58.171,48.26) PUSB1.2@56.551,48.26 ; PPI2.9@55.88,57.924 cw(c55.88,56.727) 56.727,57.573 cw(c57.573,58.42) PPI2.9@56.376,58.42 ; v1@63.231,65.674 ccw(c62.58,66.325) 63.5,66.325 ccw(c64.42,66.325) v1@63.769,65.674 ; v1(63.5,65.405) 63.5,73.152 U2.16 64.77,72.91 66.04,71.64 66.04,65.532 U1.16 ; U2.16@64.274,74.422 cw(c63.077,74.422) 63.923,73.575 cw(c64.77,72.729) U2.16@64.77,73.926 ; U2.16@64.419,74.071 cw(c63.573,73.225) 64.77,73.225 cw(c65.967,73.225) U2.16@65.121,74.071 ; U1.16@66.814,64.262 ccw(c65.617,64.262) 66.463,65.109 ccw(c67.31,65.955) U1.16@67.31,64.758 ; PL.11@93.629,46.071 ccw(c92.783,46.917) 93.98,46.917 ccw(c95.177,46.917) PL.11@94.331,46.071 ; BT01.2@93.629,47.909 cw(c92.783,47.063) 93.98,47.063 cw(c95.177,47.063) BT01.2@94.331,47.909 ; BT01.2@93.629,48.611 ccw(c92.783,49.457) 93.98,49.457 ccw(c95.177,49.457) BT01.2@94.331,48.611 ; BT02.2@93.629,50.449 cw(c92.783,49.603) 93.98,49.603 cw(c95.177,49.603) BT02.2@94.331,50.449 ; BT02.2@93.629,51.151 ccw(c92.783,51.997) 93.98,51.997 ccw(c95.177,51.997) BT02.2@94.331,51.151 ; BT03.2@93.629,52.989 cw(c92.783,52.143) 93.98,52.143 cw(c95.177,52.143) BT03.2@94.331,52.989 ; PL.11 BT01.2 BT02.2 BT03.2
  Bottom Layer w0.508: PUSB1.2@55.88,47.589 cw(c55.88,45.969) 57.025,47.115 cw(c58.171,48.26) PUSB1.2@56.551,48.26 ; PUSB1.2 59.792,44.348 69.215,44.348 69.85,44.983 69.85,46.99 BT04.2 76.2,48.26 83.232,48.26 85.09,46.402 85.09,45.085 85.725,44.45 86.995,44.45 87.63,45.085 87.63,46.402 92.028,50.8 BT02.2 ; PPI2.9 56.952,59.492 56.952,60.08 62.277,65.405 v1(63.5,65.405) ; PPI2.9@55.88,58.916 ccw(c55.88,60.113) 56.727,59.267 ccw(c57.573,58.42) PPI2.9@56.376,58.42 ; v1@63.231,65.136 ccw(c62.58,64.485) 62.58,65.405 ccw(c62.58,66.325) v1@63.231,65.674 ; BT04.2@73.164,50.8 cw(c71.967,50.8) 72.813,49.953 cw(c73.66,49.107) 73.66,50.304 cw(c73.66,49.107) 74.507,49.953 cw(c75.353,50.8) BT04.2@74.156,50.8 ; BT02.2@93.629,50.449 ccw(c92.783,49.603) 92.783,50.8 ccw(c92.783,51.997) BT02.2@93.629,51.151
pads on no net: PPI2.6 PPI2.8 U2.7 U2.9 U2.10 U2.11 U2.12 U2.13

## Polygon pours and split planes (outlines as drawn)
GND on Top Layer "Top Layer-No Net" (solid, remove dead copper): 50.8,43.688 50.8,91.44 98.552,91.44 98.806,91.186 98.806,43.434 51.054,43.434
GND on Bottom Layer "Top Layer-No Net" (solid, remove dead copper): 50.8,91.44 98.806,91.44 98.806,43.434 98.552,43.18 50.8,43.18 50.8,91.44

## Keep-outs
Keep-Out Layer:
  lines w0.254: 50.8,43.18 98.806,43.18 98.806,91.44 50.8,91.44 50.8,43.18

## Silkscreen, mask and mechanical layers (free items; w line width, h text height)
Top Overlay:
  text "B1" at 53.34,88.9 h1.52
  text "B2" at 58.928,88.9 h1.52
  text "B3" at 66.04,88.9 h1.52
  text "B4" at 71.628,88.9 h1.52
  text "B6" at 84.328,88.9 h1.52
  text "B5" at 79.275,88.8 h1.52
  text "B7" at 96.012,88.392 h1.52
  text "B8" at 96.012,82.804 h1.52
  text "11" at 55.372,80.772 h1.5
  text "1" at 51.308,78.232 h1.5
  text "4.7K" at 65.024,75.692 h0.7
  text "4.7K" at 68.58,75.692 h0.7
  text "4.7K" at 72.136,75.68 h0.7
  text "4.7K" at 76.2,75.692 h0.7
  text "4.7K" at 80.264,75.692 h0.7
  text "B9" at 95.783,75.692 h1.52
  text "B10" at 96.012,70.612 h0.7
  text "5" at 51.308,68.072 h1.5
  text "15" at 57.404,67.564 h1.5
  text "GND" at 84.328,66.548 h0.7
  text "BVCC" at 95.657,63.808 h0.7
  text "1K" at 60.452,62.484 h0.7
  text "BGND" at 95.504,57.912 h0.7
  text "VCC" at 92.964,54.864 h0.7
  text "GND" at 95.91,54.854 h0.7
  text "GND" at 84.338,54.635 h0.7
  text "10" at 51.308,52.832 h1.5
  text "20" at 54.864,52.832 h1.5
  text "GND" at 75.692,48.26 h0.7
  text "GND" at 60.452,45.72 h0.7
Bottom Overlay:
  text "4.7K" at 67.056,75.692 h0.7
  text "4.7K" at 70.612,75.692 h0.7
  text "4.7K" at 74.168,75.68 h0.7
  text "4.7K" at 78.122,75.7 h0.7
  text "4.7K" at 82.296,75.692 h0.7
  text "By Zhang Di" at 82.55,53.848 h1.52
  text "2018.11.04" at 82.465,51.964 h0.76
Mechanical 1:
  lines w0.254: 50.8,43.18 51.054,43.434 98.806,43.434 98.806,91.44 50.8,91.44 50.8,43.18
